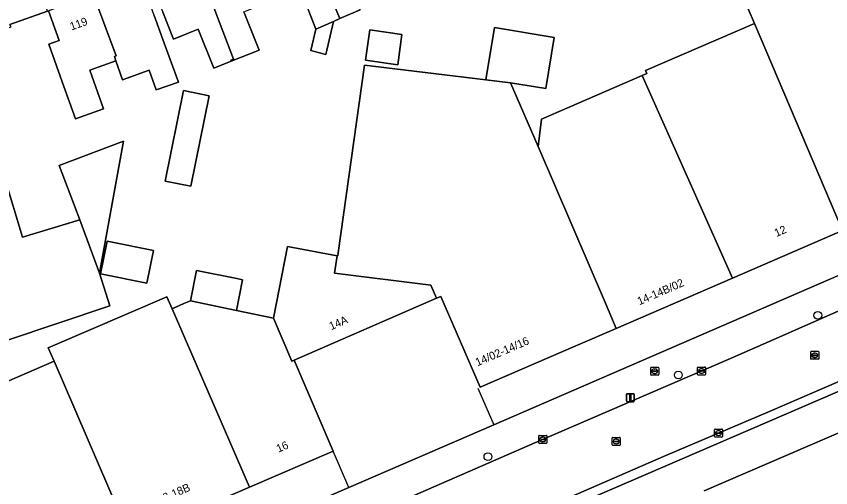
# Model space of a CAD drawing. Extents: x 158086 to 159499, y 382904 to 383981.
# Drawn here: x 158795.7 to 158897.5, y 383089.9 to 383148.8 of the extents above; entities that cross this region are included whole.
import ezdxf

# ---------------------------------------------------------------- set-up
doc = ezdxf.new("R2010")
doc.units = 0
for name, color, linetype in [('IMGEO_Boom', 7, 'Continuous'), ('IMGEO_Brandkraan', 7, 'Continuous'), ('IMGEO_Erf', 7, 'Continuous'), ('IMGEO_Hek', 7, 'Continuous'), ('IMGEO_Kolk', 7, 'Continuous'), ('IMGEO_Lichtmast', 7, 'Continuous'), ('IMGEO_Pand', 7, 'Continuous'), ('IMGEO_Pand_nummerreeks', 7, 'Continuous'), ('IMGEO_Parkeervlak_open', 7, 'Continuous'), ('IMGEO_Rijbaan_lokaal_open', 7, 'Continuous'), ('IMGEO_Rioolput', 7, 'Continuous'), ('IMGEO_Voetpad_open', 7, 'Continuous')]:
    doc.layers.add(name, color=color, linetype=linetype)

msp = doc.modelspace()

# ---------------------------------------------------------------- linework, layer by layer
at = {"layer": 'IMGEO_Boom'}
for centre in [(158895.87, 383111.4), (158878.44, 383103.94), (158854.64, 383093.74)]:
    msp.add_circle(centre, 0.489, dxfattribs=at)
at = {"layer": 'IMGEO_Brandkraan'}
for p, q in [((158874.98, 383103.99), (158874.98, 383104.84)), ((158875.05, 383104.91), (158875.91, 383104.91)), ((158875.28, 383104.46), (158875.68, 383104.46)), ((158875.47, 383104.69), (158875.49, 383104.69)), ((158875.98, 383104.84), (158875.98, 383103.99)), ((158875.91, 383103.91), (158875.05, 383103.91)), ((158875.24, 383104.41), (158875.24, 383104.42)), ((158875.68, 383104.37), (158875.28, 383104.37)), ((158875.49, 383104.13), (158875.46, 383104.13)), ((158875.72, 383104.42), (158875.72, 383104.41))]:
    msp.add_line(p, q, dxfattribs=at)
for points in [[(158874.98, 383103.99), (158874.98, 383104.84)], [(158875.05, 383104.91), (158875.91, 383104.91)], [(158875.98, 383104.84), (158875.98, 383103.99)], [(158875.91, 383103.91), (158875.05, 383103.91)]]:
    msp.add_lwpolyline(points, dxfattribs=at)
for centre, radius, start, end in [((158875.06, 383104.84), 0.0765, 91.552, 178.448), ((158875.06, 383104.84), 0.0765, 91.552, 178.448), ((158875.28, 383104.42), 0.0403, 85.8775, 175.7526), ((158875.68, 383104.42), 0.0386, 1.7309, 96.639), ((158875.9, 383104.84), 0.0765, 1.552, 88.448), ((158875.9, 383104.84), 0.0765, 1.552, 88.448), ((158875.06, 383103.99), 0.0765, 181.552, 268.448), ((158875.06, 383103.99), 0.0765, 181.552, 268.448), ((158875.27, 383104.41), 0.0366, 178.938, 274.7102), ((158875.68, 383104.41), 0.043, 264.8664, 352.4533), ((158875.9, 383103.99), 0.0765, 271.552, 358.448), ((158875.9, 383103.99), 0.0765, 271.552, 358.448)]:
    msp.add_arc(centre, radius, start, end, dxfattribs=at)
for centre, major_axis, ratio, start_param, end_param in [((158875.47, 383104.41), (-0.387, 0.002), 0.722429, 4.712389, 7.853982), ((158875.49, 383104.41), (-0.39, 0.002), 0.717154, 1.570796, 4.712389)]:
    msp.add_ellipse(centre, major_axis=major_axis, ratio=ratio, start_param=start_param, end_param=end_param, dxfattribs=at)
at = {"layer": 'IMGEO_Erf'}
for points in [[(158783.76, 383098.48), (158800.42, 383105.66), (158799.7, 383107.34), (158814.52, 383113.72), (158815.17, 383112.22), (158815.35, 383112.3), (158816.65, 383112.86), (158817.47, 383113.21), (158818.21, 383116.98), (158823.26, 383115.99), (158823.97, 383115.85), (158823.21, 383112.02), (158827.84, 383111.06), (158829.61, 383119.98), (158835.79, 383118.82), (158835.88, 383118.81), (158835.93, 383119.21), (158839.23, 383142.66), (158854.38, 383140.83), (158855.46, 383147.36), (158862.93, 383146.13), (158861.87, 383139.72), (158857.47, 383140.45), (158860.93, 383132.48), (158861.33, 383135.9), (158873.92, 383141.36), (158874.5, 383141.61), (158874.34, 383141.98), (158887.94, 383147.88), (158885.59, 383153.41)], [(158838.66, 383149.58), (158836.14, 383148.48), (158835.34, 383148.13), (158834.39, 383144), (158832.49, 383144.47), (158833.15, 383147.17), (158831.27, 383152.03)], [(158799.62, 383149.4), (158794.91, 383147.73)], [(158812.93, 383148.86), (158814.2, 383145.42), (158815.96, 383140.55), (158813.2, 383139.56), (158812.32, 383142.01), (158808.99, 383140.81), (158808.13, 383143.2), (158804.88, 383142.04), (158806.61, 383137.2), (158803.11, 383135.94), (158801.45, 383140.57), (158799.76, 383145.28), (158801.06, 383145.74), (158799.74, 383149.44)], [(158824.15, 383149.3), (158826.05, 383144.53), (158822.57, 383143.14), (158820.37, 383142.27), (158818.43, 383147.14), (158815.35, 383145.92), (158814.01, 383149.26)], [(158975.23, 383135.03), (158942.88, 383121.07), (158936.85, 383118.47), (158837.98, 383075.8), (158837.57, 383075.63), (158818.81, 383067.47), (158817.77, 383067.02)], [(158881.65, 383089.45), (158938.9, 383114.12), (158941.83, 383107.31), (158975.62, 383119.87), (158974.02, 383124.18), (158978.43, 383125.82), (158980.06, 383121.43), (158979.8, 383121.34), (158983.3, 383111.92), (158982.52, 383111.63), (158984.16, 383107.23), (158984.81, 383107.48), (158991.95, 383088.29)]]:
    msp.add_lwpolyline(points, dxfattribs=at)
for points in [[(158839.89, 383147.07), (158843.9, 383146.5), (158843.37, 383142.71), (158839.36, 383143.27)], [(158816.58, 383139.47), (158819.8, 383138.83), (158817.53, 383127.53), (158814.31, 383128.18)], [(158809.1, 383133.16), (158806.11, 383116.67), (158807.38, 383112.58), (158794.37, 383108.2), (158783.12, 383104.42), (158782.34, 383114.77), (158781.97, 383114.67), (158781.66, 383118.3), (158780.49, 383122.12), (158783.56, 383122.95), (158785.07, 383117.33), (158791.05, 383118.94), (158788.68, 383126.82), (158794.26, 383128.51), (158796.49, 383121.18), (158803.62, 383123.34), (158801.05, 383130.1)], [(158812.83, 383119.51), (158812.02, 383115.43), (158806.24, 383116.57), (158807.05, 383120.65)]]:
    msp.add_lwpolyline(points, close=True, dxfattribs=at)
at = {"layer": 'IMGEO_Hek'}
for points in [[(158853.38, 383102.3), (158855.36, 383097.72)], [(158837.27, 383089.88), (158835.29, 383094.43)]]:
    msp.add_lwpolyline(points, dxfattribs=at)
at = {"layer": 'IMGEO_Kolk'}
for p, q in [((158880.84, 383104.02), (158880.84, 383104.87)), ((158880.91, 383104.94), (158881.76, 383104.94)), ((158881.09, 383104.44), (158881.09, 383104.45)), ((158881.14, 383104.49), (158881.54, 383104.49)), ((158881.32, 383104.72), (158881.35, 383104.72)), ((158881.58, 383104.45), (158881.58, 383104.44)), ((158881.84, 383104.87), (158881.84, 383104.02)), ((158881.76, 383103.94), (158880.91, 383103.94)), ((158881.53, 383104.4), (158881.13, 383104.4)), ((158881.35, 383104.16), (158881.32, 383104.16)), ((158860.99, 383095.47), (158860.99, 383096.32)), ((158861.07, 383096.39), (158861.92, 383096.39)), ((158861.99, 383096.32), (158861.99, 383095.47)), ((158882.96, 383096.26), (158882.96, 383097.11)), ((158883.03, 383097.18), (158883.88, 383097.18)), ((158883.21, 383096.68), (158883.21, 383096.69)), ((158883.65, 383096.64), (158883.25, 383096.64)), ((158883.26, 383096.73), (158883.65, 383096.73)), ((158883.44, 383096.96), (158883.47, 383096.96)), ((158883.47, 383096.4), (158883.44, 383096.4)), ((158883.7, 383096.69), (158883.7, 383096.68)), ((158883.96, 383097.11), (158883.96, 383096.26)), ((158861.92, 383095.39), (158861.07, 383095.39)), ((158861.25, 383095.89), (158861.25, 383095.9)), ((158861.69, 383095.85), (158861.29, 383095.85)), ((158861.3, 383095.94), (158861.69, 383095.94)), ((158861.48, 383096.17), (158861.51, 383096.17)), ((158861.5, 383095.61), (158861.48, 383095.61)), ((158861.74, 383095.9), (158861.74, 383095.89)), ((158883.88, 383096.18), (158883.03, 383096.18))]:
    msp.add_line(p, q, dxfattribs=at)
for points in [[(158880.84, 383104.02), (158880.84, 383104.87)], [(158880.91, 383104.94), (158881.76, 383104.94)], [(158881.84, 383104.87), (158881.84, 383104.02)], [(158881.76, 383103.94), (158880.91, 383103.94)], [(158860.99, 383095.47), (158860.99, 383096.32)], [(158861.07, 383096.39), (158861.92, 383096.39)], [(158861.99, 383096.32), (158861.99, 383095.47)], [(158882.96, 383096.26), (158882.96, 383097.11)], [(158883.03, 383097.18), (158883.88, 383097.18)], [(158883.96, 383097.11), (158883.96, 383096.26)], [(158861.92, 383095.39), (158861.07, 383095.39)], [(158883.88, 383096.18), (158883.03, 383096.18)]]:
    msp.add_lwpolyline(points, dxfattribs=at)
for centre, radius, start, end in [((158880.91, 383104.87), 0.0765, 91.552, 178.448), ((158880.91, 383104.87), 0.0765, 91.552, 178.448), ((158881.14, 383104.45), 0.0403, 85.8775, 175.7526), ((158881.13, 383104.44), 0.0366, 178.938, 274.7102), ((158881.54, 383104.44), 0.043, 264.8664, 352.4533), ((158881.54, 383104.45), 0.0386, 1.7309, 96.639), ((158881.76, 383104.87), 0.0765, 1.552, 88.448), ((158881.76, 383104.87), 0.0765, 1.552, 88.448), ((158880.91, 383104.02), 0.0765, 181.552, 268.448), ((158880.91, 383104.02), 0.0765, 181.552, 268.448), ((158881.76, 383104.02), 0.0765, 271.552, 358.448), ((158881.76, 383104.02), 0.0765, 271.552, 358.448), ((158861.07, 383096.32), 0.0765, 91.552, 178.448), ((158861.07, 383096.32), 0.0765, 91.552, 178.448), ((158861.92, 383096.32), 0.0765, 1.552, 88.448), ((158861.92, 383096.32), 0.0765, 1.552, 88.448), ((158883.03, 383097.11), 0.0765, 91.552, 178.448), ((158883.03, 383097.11), 0.0765, 91.552, 178.448), ((158883.25, 383096.69), 0.0403, 85.8775, 175.7526), ((158883.25, 383096.68), 0.0366, 178.938, 274.7102), ((158883.66, 383096.69), 0.0386, 1.7309, 96.639), ((158883.66, 383096.68), 0.043, 264.8664, 352.4533), ((158883.88, 383097.11), 0.0765, 1.552, 88.448), ((158883.88, 383097.11), 0.0765, 1.552, 88.448), ((158861.07, 383095.47), 0.0765, 181.552, 268.448), ((158861.07, 383095.47), 0.0765, 181.552, 268.448), ((158861.29, 383095.9), 0.0403, 85.8775, 175.7526), ((158861.29, 383095.89), 0.0366, 178.938, 274.7102), ((158861.7, 383095.9), 0.0386, 1.7309, 96.639), ((158861.69, 383095.89), 0.043, 264.8664, 352.4533), ((158861.92, 383095.47), 0.0765, 271.552, 358.448), ((158861.92, 383095.47), 0.0765, 271.552, 358.448), ((158883.03, 383096.26), 0.0765, 181.552, 268.448), ((158883.03, 383096.26), 0.0765, 181.552, 268.448), ((158883.88, 383096.26), 0.0765, 271.552, 358.448), ((158883.88, 383096.26), 0.0765, 271.552, 358.448)]:
    msp.add_arc(centre, radius, start, end, dxfattribs=at)
for centre, major_axis, ratio, start_param, end_param in [((158881.32, 383104.44), (-0.387, 0.002), 0.722429, 4.712389, 7.853982), ((158881.35, 383104.44), (-0.39, 0.002), 0.717154, 1.570796, 4.712389), ((158883.44, 383096.68), (-0.387, 0.002), 0.722429, 4.712389, 7.853982), ((158883.47, 383096.68), (-0.39, 0.002), 0.717154, 1.570796, 4.712389), ((158861.48, 383095.89), (-0.387, 0.002), 0.722429, 4.712389, 7.853982), ((158861.5, 383095.89), (-0.39, 0.002), 0.717154, 1.570796, 4.712389)]:
    msp.add_ellipse(centre, major_axis=major_axis, ratio=ratio, start_param=start_param, end_param=end_param, dxfattribs=at)
at = {"layer": 'IMGEO_Lichtmast'}
for p, q in [((158871.94, 383100.7), (158871.94, 383101.5)), ((158871.94, 383101.5), (158871.94, 383100.7)), ((158872.04, 383101.6), (158872.83, 383101.6)), ((158872.83, 383101.6), (158872.04, 383101.6)), ((158872.93, 383101.5), (158872.93, 383100.7)), ((158872.93, 383100.7), (158872.93, 383101.5)), ((158872.83, 383100.6), (158872.04, 383100.6)), ((158872.04, 383100.6), (158872.83, 383100.6))]:
    msp.add_line(p, q, dxfattribs=at)
msp.add_lwpolyline([(158872.36, 383101.47), (158872.51, 383101.47), (158872.51, 383100.72), (158872.36, 383100.72), (158872.36, 383101.47)], dxfattribs=at)
for centre, start, end in [((158872.04, 383101.5), 90, 180), ((158872.04, 383101.5), 90, 180), ((158872.83, 383101.5), 0, 90), ((158872.83, 383101.5), 360, 90), ((158872.04, 383100.7), 180, 270), ((158872.04, 383100.7), 180, 270), ((158872.83, 383100.7), 270, 0), ((158872.83, 383100.7), 270, 0)]:
    msp.add_arc(centre, 0.1, start, end, dxfattribs=at)
at = {"layer": 'IMGEO_Pand'}
for points in [[(158835.86, 383163.73), (158830.62, 383161.46), (158836.02, 383148.78), (158836.14, 383148.48), (158838.66, 383149.58), (158836.91, 383154.23), (158839.49, 383155.35)], [(158830.62, 383161.46), (158824.8, 383158.93), (158826.77, 383154.34), (158828.29, 383150.77), (158831.27, 383152.03), (158833.15, 383147.17), (158835.34, 383148.13), (158836.14, 383148.48), (158836.02, 383148.78)], [(158887.94, 383147.88), (158898.94, 383122), (158899.42, 383122.21), (158899.15, 383122.85), (158912.66, 383128.71), (158912.93, 383128.09), (158913.1, 383128.17), (158899.18, 383160.5), (158891.2, 383156.52), (158891.31, 383156.29), (158885.59, 383153.41)], [(158817.96, 383156.22), (158822.83, 383143.41), (158822.51, 383143.28), (158822.57, 383143.14), (158826.05, 383144.53), (158824.15, 383149.3), (158827.07, 383150.47), (158825.7, 383153.92), (158823.85, 383158.56)], [(158817.96, 383156.22), (158812.16, 383153.91), (158814.01, 383149.26), (158815.35, 383145.92), (158818.43, 383147.14), (158820.37, 383142.27), (158822.57, 383143.14), (158822.51, 383143.28), (158822.83, 383143.41)], [(158805.36, 383151.46), (158808.19, 383143.81), (158807.97, 383143.73), (158808.13, 383143.2), (158808.99, 383140.81), (158812.32, 383142.01), (158813.2, 383139.56), (158815.96, 383140.55), (158814.2, 383145.42), (158812.93, 383148.86), (158811.25, 383153.57)], [(158805.36, 383151.46), (158799.74, 383149.44), (158801.06, 383145.74), (158799.76, 383145.28), (158801.45, 383140.57), (158803.11, 383135.94), (158806.61, 383137.2), (158804.88, 383142.04), (158808.13, 383143.2), (158807.97, 383143.73), (158808.19, 383143.81)], [(158835.34, 383148.13), (158833.15, 383147.17), (158832.49, 383144.47), (158834.39, 383144)], [(158862.93, 383146.13), (158855.46, 383147.36), (158854.38, 383140.83), (158857.47, 383140.45), (158861.87, 383139.72)], [(158887.94, 383147.88), (158874.34, 383141.98), (158874.5, 383141.61), (158873.92, 383141.36), (158885.2, 383116.05), (158898.94, 383122)], [(158843.37, 383142.71), (158843.9, 383146.5), (158839.89, 383147.07), (158839.36, 383143.27)], [(158860.93, 383132.48), (158857.47, 383140.45), (158854.38, 383140.83), (158839.23, 383142.66), (158835.93, 383119.21), (158835.88, 383118.81), (158835.79, 383118.82), (158835.48, 383116.67), (158847.51, 383115.15), (158848.21, 383113.52), (158848.76, 383113.75), (158853.66, 383102.42), (158865.61, 383107.58), (158870.67, 383109.76), (158869.32, 383112.91)], [(158873.92, 383141.36), (158861.33, 383135.9), (158860.93, 383132.48), (158869.32, 383112.91), (158870.67, 383109.76), (158885.2, 383116.05)], [(158819.8, 383138.83), (158816.58, 383139.47), (158814.31, 383128.18), (158817.53, 383127.53)], [(158809.1, 383133.16), (158801.05, 383130.1), (158803.62, 383123.34), (158806.11, 383116.67)], [(158803.62, 383123.34), (158796.49, 383121.18), (158794.26, 383128.51), (158788.68, 383126.82), (158791.05, 383118.94), (158791.18, 383118.5), (158794.37, 383108.2), (158807.38, 383112.58), (158806.11, 383116.67)], [(158806.24, 383116.57), (158812.02, 383115.43), (158812.83, 383119.51), (158807.05, 383120.65)], [(158848.21, 383113.52), (158847.51, 383115.15), (158835.48, 383116.67), (158835.79, 383118.82), (158829.61, 383119.98), (158827.84, 383111.06), (158830.13, 383105.67), (158830.42, 383105.79)], [(158823.21, 383112.02), (158823.97, 383115.85), (158823.26, 383115.99), (158818.21, 383116.98), (158817.47, 383113.21)], [(158815.17, 383112.22), (158814.52, 383113.72), (158799.7, 383107.34), (158800.42, 383105.66), (158809.97, 383083.53), (158820.88, 383088.23), (158824.86, 383089.94)], [(158830.42, 383105.79), (158830.13, 383105.67), (158827.84, 383111.06), (158823.21, 383112.02), (158817.47, 383113.21), (158816.65, 383112.86), (158815.35, 383112.3), (158815.17, 383112.22), (158824.86, 383089.94), (158835.29, 383094.43)], [(158783.76, 383098.48), (158793.29, 383076.34), (158795.61, 383077.34), (158809.97, 383083.53), (158800.42, 383105.66)]]:
    msp.add_lwpolyline(points, close=True, dxfattribs=at)
msp.add_lwpolyline([(158957.71, 383070.48), (158945.75, 383098.2), (158941.83, 383107.31), (158938.9, 383114.12), (158881.65, 383089.45)], dxfattribs=at)
at = {"layer": 'IMGEO_Parkeervlak_open'}
for points in [[(158855.36, 383097.72), (158904.77, 383119.14), (158915.08, 383123.6), (158913.1, 383128.17), (158912.93, 383128.09), (158912.66, 383128.71), (158899.15, 383122.85), (158899.42, 383122.21), (158898.94, 383122), (158885.2, 383116.05), (158870.67, 383109.76), (158865.61, 383107.58), (158853.66, 383102.42), (158848.76, 383113.75), (158848.21, 383113.52), (158830.42, 383105.79), (158835.29, 383094.43), (158824.86, 383089.94), (158820.88, 383088.23)], [(158812.08, 383078.95), (158814.26, 383079.89), (158822.73, 383083.52), (158826.96, 383085.41), (158837.27, 383089.88), (158855.36, 383097.72)]]:
    msp.add_lwpolyline(points, dxfattribs=at)
at = {"layer": 'IMGEO_Rijbaan_lokaal_open'}
for points in [[(158901.63, 383113.35), (158890.38, 383108.37), (158884.68, 383105.89), (158869.57, 383099.36), (158860.52, 383095.47), (158837.17, 383085.32)], [(158861.17, 383087.04), (158876.57, 383093.74), (158889.93, 383099.44), (158919.97, 383112.43)]]:
    msp.add_lwpolyline(points, dxfattribs=at)
at = {"layer": 'IMGEO_Rioolput'}
for p, q in [((158894.98, 383105.97), (158894.98, 383106.82)), ((158895.05, 383106.9), (158895.9, 383106.9)), ((158895.46, 383106.68), (158895.49, 383106.68)), ((158895.98, 383106.82), (158895.98, 383105.97)), ((158895.9, 383105.9), (158895.05, 383105.9)), ((158895.23, 383106.39), (158895.23, 383106.4)), ((158895.67, 383106.35), (158895.27, 383106.35)), ((158895.28, 383106.44), (158895.68, 383106.44)), ((158895.49, 383106.12), (158895.46, 383106.12)), ((158895.72, 383106.4), (158895.72, 383106.39)), ((158870.17, 383095.21), (158870.17, 383096.07)), ((158870.25, 383096.14), (158871.1, 383096.14)), ((158870.43, 383095.63), (158870.43, 383095.65)), ((158870.87, 383095.6), (158870.47, 383095.6)), ((158870.48, 383095.68), (158870.87, 383095.68)), ((158870.66, 383095.92), (158870.69, 383095.92)), ((158870.68, 383095.36), (158870.66, 383095.36)), ((158870.92, 383095.65), (158870.92, 383095.63)), ((158871.17, 383096.07), (158871.17, 383095.21)), ((158871.1, 383095.14), (158870.25, 383095.14))]:
    msp.add_line(p, q, dxfattribs=at)
for points in [[(158894.98, 383105.97), (158894.98, 383106.82)], [(158895.05, 383106.9), (158895.9, 383106.9)], [(158895.98, 383106.82), (158895.98, 383105.97)], [(158895.9, 383105.9), (158895.05, 383105.9)], [(158870.17, 383095.21), (158870.17, 383096.07)], [(158870.25, 383096.14), (158871.1, 383096.14)], [(158871.17, 383096.07), (158871.17, 383095.21)], [(158871.1, 383095.14), (158870.25, 383095.14)]]:
    msp.add_lwpolyline(points, dxfattribs=at)
for centre, radius, start, end in [((158895.05, 383106.82), 0.0765, 91.552, 178.448), ((158895.05, 383106.82), 0.0765, 91.552, 178.448), ((158895.9, 383106.82), 0.0765, 1.552, 88.448), ((158895.9, 383106.82), 0.0765, 1.552, 88.448), ((158895.05, 383105.97), 0.0765, 181.552, 268.448), ((158895.05, 383105.97), 0.0765, 181.552, 268.448), ((158895.28, 383106.4), 0.0403, 85.8775, 175.7526), ((158895.27, 383106.39), 0.0366, 178.938, 274.7102), ((158895.68, 383106.4), 0.043, 264.8664, 352.4533), ((158895.68, 383106.4), 0.0386, 1.7309, 96.639), ((158895.9, 383105.97), 0.0765, 271.552, 358.448), ((158895.9, 383105.97), 0.0765, 271.552, 358.448), ((158870.25, 383096.06), 0.0765, 91.552, 178.448), ((158870.25, 383096.06), 0.0765, 91.552, 178.448), ((158870.47, 383095.64), 0.0403, 85.8775, 175.7526), ((158870.47, 383095.63), 0.0366, 178.938, 274.7102), ((158870.88, 383095.64), 0.0386, 1.7309, 96.639), ((158870.87, 383095.64), 0.043, 264.8664, 352.4533), ((158871.1, 383096.06), 0.0765, 1.552, 88.448), ((158871.1, 383096.06), 0.0765, 1.552, 88.448), ((158870.25, 383095.22), 0.0765, 181.552, 268.448), ((158870.25, 383095.22), 0.0765, 181.552, 268.448), ((158871.1, 383095.22), 0.0765, 271.552, 358.448), ((158871.1, 383095.22), 0.0765, 271.552, 358.448)]:
    msp.add_arc(centre, radius, start, end, dxfattribs=at)
for centre, major_axis, ratio, start_param, end_param in [((158895.46, 383106.4), (-0.387, 0.002), 0.722429, 4.712389, 7.853982), ((158895.49, 383106.4), (-0.39, 0.002), 0.717154, 1.570796, 4.712389), ((158870.66, 383095.64), (-0.387, 0.002), 0.722429, 4.712389, 7.853982), ((158870.68, 383095.64), (-0.39, 0.002), 0.717154, 1.570796, 4.712389)]:
    msp.add_ellipse(centre, major_axis=major_axis, ratio=ratio, start_param=start_param, end_param=end_param, dxfattribs=at)
at = {"layer": 'IMGEO_Voetpad_open'}
for points in [[(158795.04, 383147.44), (158794.91, 383147.73), (158799.62, 383149.4), (158798.56, 383152.3), (158796.62, 383151.6), (158789.24, 383148.95), (158790.33, 383145.81)], [(158860.52, 383095.47), (158869.57, 383099.36), (158884.68, 383105.89), (158890.38, 383108.37), (158901.63, 383113.35), (158906.77, 383115.5), (158904.77, 383119.14), (158855.36, 383097.72), (158837.27, 383089.88), (158826.96, 383085.41), (158822.73, 383083.52), (158814.26, 383079.89), (158815.75, 383076.1), (158823.95, 383079.66), (158837.17, 383085.32)], [(158936.39, 383119.54), (158919.97, 383112.43), (158889.93, 383099.44), (158876.57, 383093.74), (158861.17, 383087.04), (158841.7, 383078.51), (158837.57, 383076.75), (158837.98, 383075.8), (158936.85, 383118.47), (158936.59, 383119.09)]]:
    msp.add_lwpolyline(points, close=True, dxfattribs=at)

# ---------------------------------------------------------------- texts
at = {"layer": 'IMGEO_Pand_nummerreeks'}
for s, rotation, p in [('119', 19.7153, (158802.6, 383146.98)), ('12', 23.4237, (158890.69, 383121.17)), ('14-14B/02', 23.4168, (158873.57, 383112.65)), ('14A', 23.3018, (158835.05, 383109.53)), ('14/02-14/16', 23.3308, (158853.33, 383105.02)), ('16', 23.3022, (158828.45, 383094.23)), ('18-18B', 23.3079, (158813.58, 383087.82))]:
    msp.add_text(s, height=1, rotation=rotation, dxfattribs=at).set_placement(p)

doc.saveas('drawing.dxf')
